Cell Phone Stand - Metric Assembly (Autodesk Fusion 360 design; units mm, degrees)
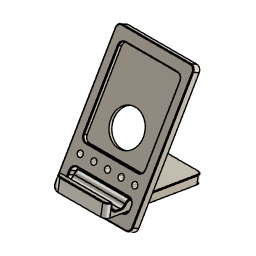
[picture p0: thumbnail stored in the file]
sketch "Main Body Sketch" plane through (0, 0, 0) normal (0, 1, 0) x axis (1, 0, 0)
  line L1 (30, 0) -> (-30, 0)
  line L2 (30, -100) -> (30, 0)
  line L3 (-30, -100) -> (30, -100)
  line L4 (-30, 0) -> (-30, -100)
  line L5 (30, -100) -> (-30, 0)
  line L6 (-30, -100) -> (30, 0)
  line L7 (23.5, -17.5) -> (-23.5, -17.5)
  line L8 (23.5, -8) -> (23.5, -17.5)
  line L9 (-23.5, -8) -> (23.5, -8)
  line L10 (-23.5, -17.5) -> (-23.5, -8)
  line L11 (0, 0) -> (0, -8)
  line L12 (23.5, -92) -> (-23.5, -92)
  line L13 (23.5, -32) -> (23.5, -92)
  line L14 (-23.5, -32) -> (23.5, -32)
  line L15 (-23.5, -92) -> (-23.5, -32)
  line L16 (0, -62.5) -> (0, -50)
  line L17 (17.2022, -62.0451) -> (0, -50)
  line L18 (21, -50) -> (0, -50)
  line L19 (17.2022, -37.9549) -> (0, -50)
  circle C1 centre (0, -50) radius 12.5
  point P6 (0, -50)
  point P1 (0, 0)
  point P11 (0, -8)
  point P12 (0, 0)
  point P17 (0, -50)
  point P21 (0, -50)
  point P22 (0, -62.5)
  point P18 (17.2022, -62.0451)
  point P23 (17.2022, -62.0451)
  point P19 (21, -50)
  point P24 (21, -50)
  point P25 (0, -50)
  point P20 (17.2022, -37.9549)
  point P26 (17.2022, -37.9549)
  point P27 (-17.2022, -62.0451)
  point P28 (-21, -50)
  point P29 (-17.2022, -37.9549)
  point P30 (0, -25)
  point P4 (30, -100)
  point P5 (-30, -100)
  point P3 (30, 0)
  point P8 (23.5, -17.5)
  point P9 (23.5, -8)
  point P7 (-23.5, -17.5)
  point P14 (23.5, -92)
  point P15 (23.5, -32)
  horizontal L1
  perpendicular L1 L2
  parallel L1 L3
  parallel L2 L4
  coincident L5 P6
  coincident L6 P6
  midpoint P1 L1
  horizontal L7
  vertical L8
  horizontal L9
  vertical L10
  midpoint L9 P11
  coincident P1 P12
  vertical L11
  horizontal L12
  vertical L13
  horizontal L14
  vertical L15
  collinear L8 L13
  collinear L10 L15
  coincident P6 P17
  coincident P6 P21
  coincident C1 P22
  vertical L16
  coincident P18 P23
  coincident P19 P24
  perpendicular L16 L18
  coincident P17 P25
  coincident P20 P26
  equal L17 L18
  equal L18 L19
  symmetric P18 L16 P27
  symmetric P19 L16 P28
  symmetric P20 L16 P29
  vertical P6 P30
  dimension "d1" distance P4 P5 = 60
  dimension "d2" distance P3 P4 = 100
  dimension "d3" distance P8 P9 = 9.5
  dimension "d4" distance L1 L9 = 8
  dimension "d5" distance P7 P8 = 47
  dimension "d6" distance L3 L12 = 8 (= "d4")
  dimension "d7" distance P14 P15 = 60
  dimension "d8" diameter C1 = 25
  dimension "d9" distance P21 P24 = 21
  dimension "d10" angle L17 L18 = 35
  dimension "d11" angle L18 L19 = 35 (= "d10")
  dimension "d12" distance P17 P30 = 25
  dimension "d15" R-Pattern1-uDistance = 21
  dimension "d16" R-Pattern1-vDistance = 0
extrude "Extrude1" new body sketch "Main Body Sketch" profile of L1 L2 L3 L4 L7 L8 L9 L10 L12 L13 L14 L15 C1 along normal blind 5.5
extrude "Extrude2" cut sketch "Main Body Sketch" profile of L12 L13 L14 L15 C1 along normal blind 3
hole "Hole2" HoleDiameter 4.234 TipAngle 118
fillet "Fillet1" radius 3.5
chamfer "Chamfer1" distance 0.5
move "Move1"
sketch "Stand Body Sketch" plane through (0, 0, 0) normal (1, 0, 0) x axis (0, 1, 0)
  line L1 (14.7999, 15.9408) -> (10.4698, 18.4408)
  line L2 (5.7198, 10.2135) -> (10.0499, 7.7135)
  line L3 (66.5456, 2.9579) -> (12.5794, 12.0948)
  line L4 (66.0448, 0) -> (66.5456, 2.9579)
  line L5 (-7.9029, 12.52) -> (66.0448, 0)
  line L6 (-6.317, 21.8867) -> (-7.9029, 12.52)
  line L7 (-2.3731, 21.2189) -> (-6.317, 21.8867)
  line L8 (-2.3281, 14.6188) -> (-2.3731, 21.2189)
  line L9 (6.5456, 13.1164) -> (-2.3281, 14.6188)
  line L10 (8.7802, 17.0486) -> (6.5456, 13.1164)
  line L11 (16.0467, 18.1003) -> (19.9906, 17.4326)
  line L12 (24.2831, 10.1133) -> (19.9906, 17.4326)
  line L13 (16.0467, 18.1003) -> (12.5794, 12.0948)
  line L14 (54.2999, 84.3568) -> (7.7999, 3.8164)
  line L15 (13.6992, 16.2157) -> (8.7802, 17.0486)
  line L16 (12.1028, 18.768) -> (11.7272, 16.5496)
  line L17 (16.0467, 18.1003) -> (12.1028, 18.768)
  line L18 (15.6711, 15.8819) -> (16.0467, 18.1003)
  line L19 (67.0881, 6.1623) -> (22.1368, 13.7729)
  line L20 (66.5456, 2.9579) -> (67.0881, 6.1623)
  circle C1 centre (13.6992, 16.2157) radius 2
  point P17 (24.2831, 10.1133)
  point P16 (16.0467, 18.1003)
  point P1 (0, 0)
  point P8 (66.0448, 0)
  point P18 (16.0467, 18.1003)
  point P5 (5.7198, 10.2135)
  point P23 (11.7272, 16.5496)
  point P26 (15.6711, 15.8819)
  point P21 (13.6992, 16.2157)
  point P22 (13.6992, 16.2157)
  point P25 (16.0467, 18.1003)
  point P28 (22.1368, 13.7729)
  point P30 (66.5456, 2.9579)
  point P7 (66.5456, 2.9579)
  point P9 (-7.9029, 12.52)
  point P10 (-6.317, 21.8867)
  point P11 (-2.3731, 21.2189)
  point P12 (-2.3281, 14.6188)
  point P13 (6.5456, 13.1164)
  point P15 (19.9906, 17.4326)
  point P14 (8.7802, 17.0486)
  point P27 (6.0499, 0.7853)
  perpendicular L3 L4
  perpendicular L5 L6
  perpendicular L6 L7
  parallel L3 L9
  coincident L3 P17
  collinear L7 L11
  perpendicular L1 L13
  coincident P16 L13
  parallel L3 L5
  horizontal P1 P8
  collinear L3 L9
  coincident P16 P18
  collinear L13 L14
  coincident P5 L5
  parallel L5 L15
  coincident C1 P23
  perpendicular L16 L17
  coincident C1 P26
  tangent C1 L18
  perpendicular L17 L18
  tangent C1 L16
  parallel L6 L16
  coincident P21 P22
  collinear L11 L17
  coincident P18 P25
  midpoint L12 P28
  perpendicular L4 L19
  coincident L3 P30
  perpendicular L3 L20
  coincident P7 P30
  dimension "d30" distance P8 P9 = 75
  dimension "d31" distance P7 P8 = 3
  dimension "d32" distance P9 P10 = 9.5
  dimension "d33" angle L11 L12 = 50
  dimension "d34" distance P10 P11 = 4
  dimension "d35" distance P12 P13 = 9
  dimension "d36" distance P15 P16 = 4
  dimension "d37" distance L9 P14 = 4.25
  dimension "d38" angle L9 L10 = 70
  dimension "d39" angle L8 L9 = 100
  dimension "d40" diameter C1 = 4
  dimension "d41" distance P8 P27 = 60
extrude "Extrude3" new body sketch "Stand Body Sketch" profile of L3 L4 L5 L6 L7 L8 L9 L10 L11 L12 L13 L14 L15 C1 L18 L19 L20 distance 40
fillet "Fillet2" radius 3.5
chamfer "Chamfer2" distance 0.5
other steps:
thread "Thread1" ThreadOffset 0 ThreadDepth 7.4
named bodies: "Main Body", "Stand Body"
